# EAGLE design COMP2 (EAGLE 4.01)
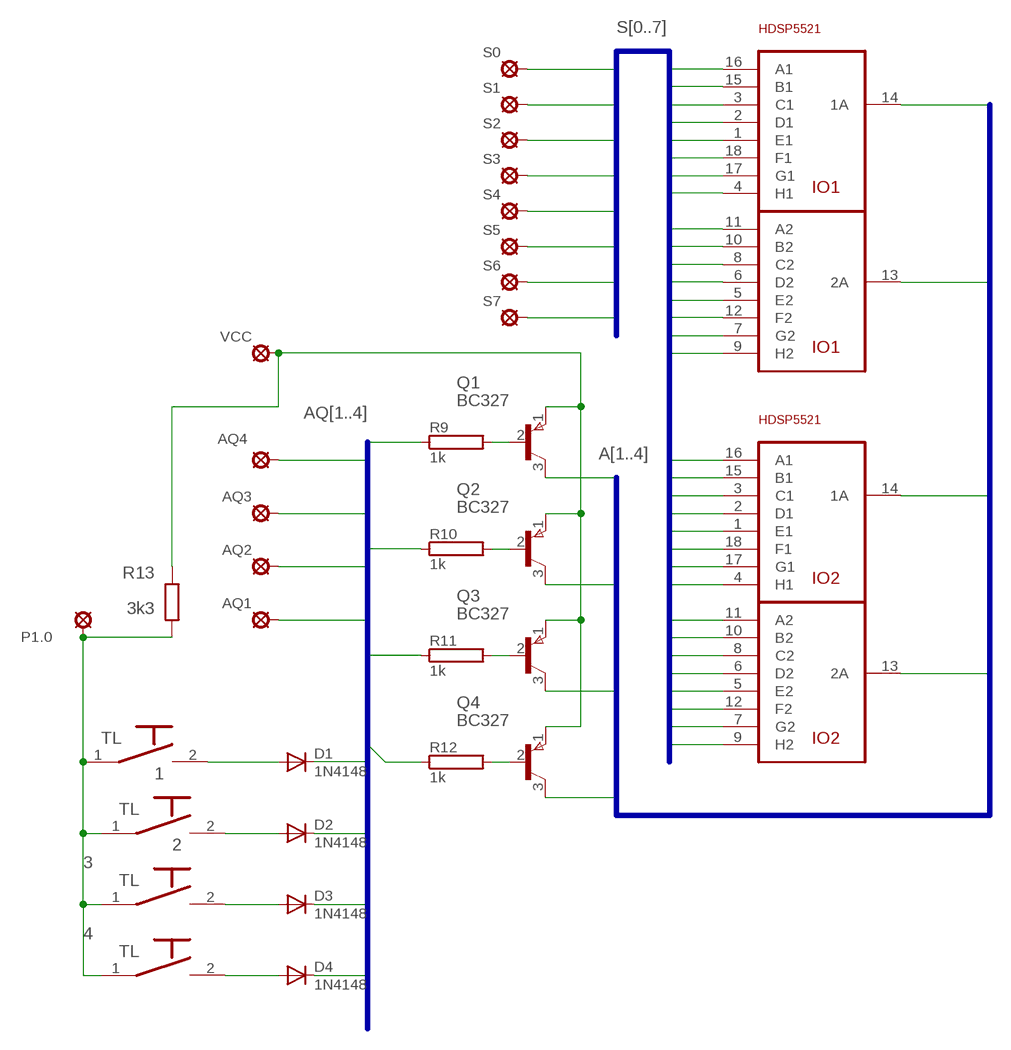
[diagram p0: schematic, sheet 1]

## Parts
1  TL  [TL]
2  TL  [TL]
3  TL  [TL]
4  TL  [TL]
AQ1  LSP10  [LSP10]
AQ2  LSP10  [LSP10]
AQ3  LSP10  [LSP10]
AQ4  LSP10  [LSP10]
D1  1N4148  [DO35-10]
D2  1N4148  [DO35-10]
D3  1N4148  [DO35-10]
D4  1N4148  [DO35-10]
IO1  HDSP5521  [HDSP5521]
IO2  HDSP5521  [HDSP5521]
P1.0  LSP10  [LSP10]
Q1  BC327  [TO92]
Q2  BC327  [TO92]
Q3  BC327  [TO92]
Q4  BC327  [TO92]
R9  1k  0309/10  [0309/10]
R10  1k  0309/10  [0309/10]
R11  1k  0309/10  [0309/10]
R12  1k  0309/10  [0309/10]
R13  3k3  RR-10  [RR-10]
S0  LSP10  [LSP10]
S1  LSP10  [LSP10]
S2  LSP10  [LSP10]
S3  LSP10  [LSP10]
S4  LSP10  [LSP10]
S5  LSP10  [LSP10]
S6  LSP10  [LSP10]
S7  LSP10  [LSP10]
VCC  LSP10  [LSP10]

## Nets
+5V: Q1.1(E) Q2.1(E) Q3.1(E) Q4.1(E) R13.2 VCC.MP
A1: IO1.14(1A) Q1.3(C)
A2: IO1.13(2A) Q2.3(C)
A3: IO2.14(1A) Q3.3(C)
A4: IO2.13(2A) Q4.3(C)
AQ1: AQ1.MP D1.K R9.1
AQ2: AQ2.MP D2.K R10.1
AQ3: AQ3.MP D3.K R11.1
AQ4: AQ4.MP D4.K R12.1
P1.0: 1.1 2.1 3.1 4.1 P1.0.MP R13.1
R9Q1: Q1.2(B) R9.2
R10Q2: Q2.2(B) R10.2
R11Q3: Q3.2(B) R11.2
R12Q4: Q4.2(B) R12.2
S0: IO1.11(A2) IO1.16(A1) IO2.11(A2) IO2.16(A1) S0.MP
S1: IO1.10(B2) IO1.15(B1) IO2.10(B2) IO2.15(B1) S1.MP
S2: IO1.3(C1) IO1.8(C2) IO2.3(C1) IO2.8(C2) S2.MP
S3: IO1.2(D1) IO1.6(D2) IO2.2(D1) IO2.6(D2) S3.MP
S4: IO1.1(E1) IO1.5(E2) IO2.1(E1) IO2.5(E2) S4.MP
S5: IO1.12(F2) IO1.18(F1) IO2.12(F2) IO2.18(F1) S5.MP
S6: IO1.7(G2) IO1.17(G1) IO2.7(G2) IO2.17(G1) S6.MP
S7: IO1.4(H1) IO1.9(H2) IO2.4(H1) IO2.9(H2) S7.MP
TL1.2: 1.2 D1.A
TL2.2: 2.2 D2.A
TL3.1: 4.2 D4.A
TL3.2: 3.2 D3.A

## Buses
S[0..7]
A[1..4]
AQ[1..4]

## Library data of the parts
1-4 = vl1:TL
AQ1-AQ4 P1.0 S0 S1-S7 VCC = SOLPAD:LSP10
D1-D4 = DIODE:1N4148
IO1 IO2 = vl1:HDSP5521
Q1-Q4 = PNP:BC327
R9-R12 = R:0309/10
R13 = GM99:RR-10

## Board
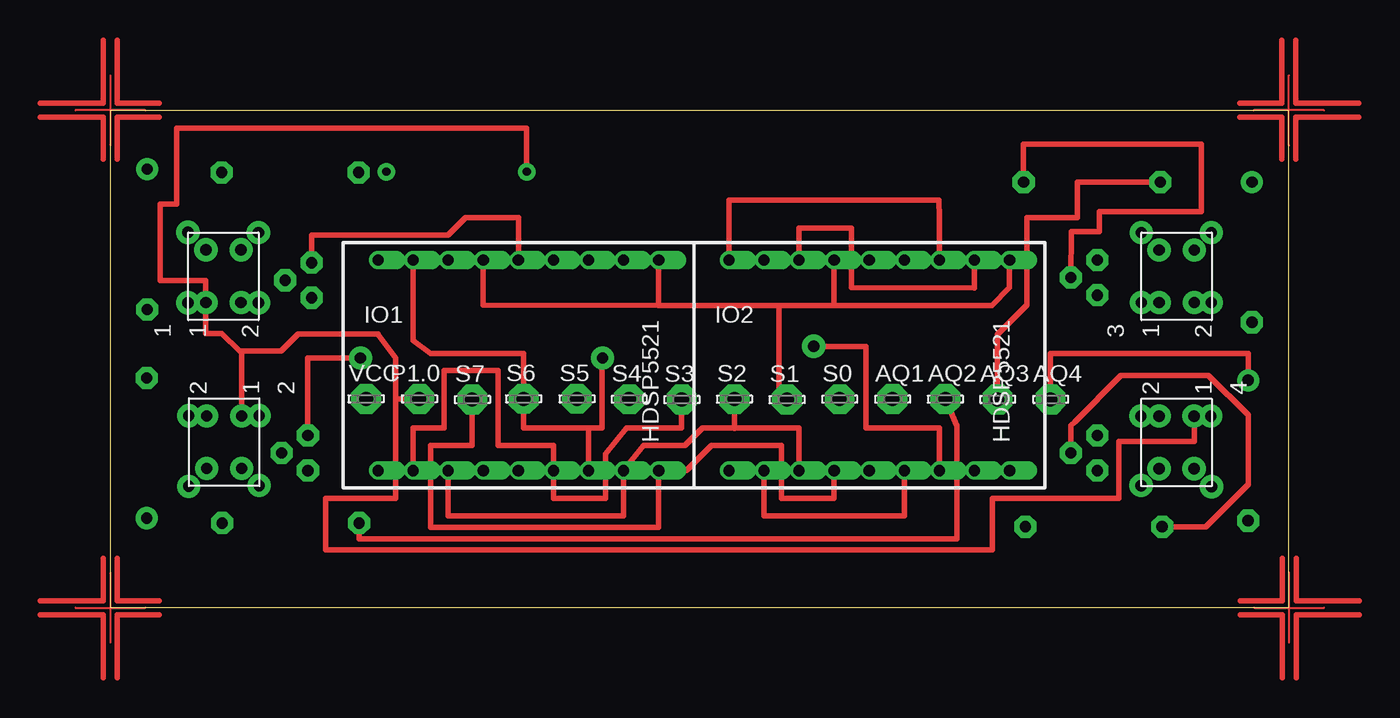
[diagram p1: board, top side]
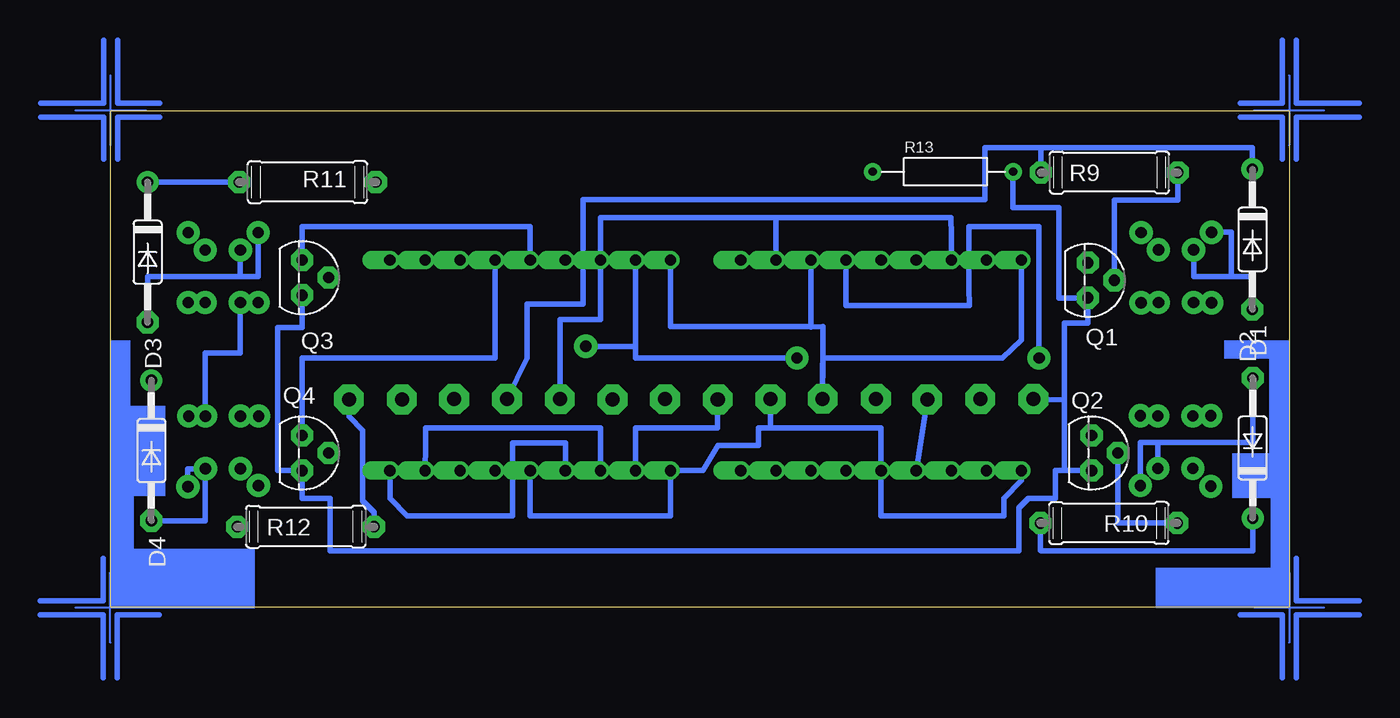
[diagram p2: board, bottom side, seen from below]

Size 85.32 x 36 mm. Coordinates in mm from the lower left corner, seen from the top.
Outline: 0,0 85.32,0 85.32,36 0,36 0,0
Copper layers used: Top, Bottom

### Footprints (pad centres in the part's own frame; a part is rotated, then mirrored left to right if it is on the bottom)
TL = drill 0.813 pad 1.676 round: 1 -6.35,1.27; 2 -2.54,1.27; 3 -6.35,-1.27; 4 -2.54,-1.27
LSP10 = drill 1.016 pad 2.159 octagon: MP 0,0
DO35-10 = drill 0.813 pad 1.6 octagon: A 5.08,0 | drill 0.813 pad 1.6 round: K -5.08,0
HDSP5521 = drill 0.813 pad 1.092 offset: 1 -10.16,-7.62; 2 -7.62,-7.62; 3 -5.08,-7.62; 4 -2.54,-7.62; 5 0,-7.62; 6 2.54,-7.62; 7 5.08,-7.62; 8 7.62,-7.62; 9 10.16,-7.62; 10 10.16,7.62; 11 7.62,7.62; 12 5.08,7.62; 13 2.54,7.62; 14 0,7.62; 15 -2.54,7.62; 16 -5.08,7.62; 17 -7.62,7.62; 18 -10.16,7.62
TO92 = drill 0.813 pad 1.6 octagon: 1 1.27,0; 2 0,1.905; 3 -1.27,0
0309/10 = drill 0.813 pad 1.6 octagon: 1 -4.953,0; 2 4.953,0
RR-10 = drill 0.61 pad 1.27 round: 1 0,0; 2 10.16,0

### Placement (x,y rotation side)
1  8.19,28.44 90 top
2  8.24,7.53 270 top
3  77.2,28.44 90 top
4  77.19,7.51 270 top
AQ1  56.63,15.1 0 top
AQ2  60.45,15.1 0 top
AQ3  64.23,15.08 0 top
AQ4  68.07,15.08 0 top
D1  2.67,26.67 270 bottom
D2  2.64,11.55 90 bottom
D3  82.65,25.74 270 bottom
D4  82.37,11.37 270 bottom
IO1  29.54,17.54 0 top
IO2  54.94,17.54 0 top
P1.0  22.37,15.11 0 top
Q1  14.57,23.7 270 bottom
Q2  14.3,11.19 270 bottom
Q3  71.45,23.89 270 bottom
Q4  71.45,11.19 270 bottom
R9  13.01,31.51 0 bottom
R10  13.05,6.12 0 bottom
R11  71.07,30.81 0 bottom
R12  71.2,5.86 180 bottom
R13  30.15,31.57 0 bottom
S0  52.8,15.09 0 top
S1  48.99,15.07 0 top
S2  45.18,15.09 0 top
S3  41.37,15.07 0 top
S4  37.56,15.09 0 top
S5  33.77,15.12 0 top
S6  29.91,15.12 0 top
S7  26.2,15.07 0 top
U$1  [ROH]  0,36.01 270 top
U$2  [ROH]  0,0 0 top
U$3  [ROH]  85.34,0 90 top
U$4  [ROH]  85.32,36.01 180 top
VCC  18.52,15.11 0 top

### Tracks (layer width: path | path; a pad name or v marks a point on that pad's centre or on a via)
+5V
  Bottom 0.406: Q3.1 71.45,20.26 73.23,20.26 73.23,9.92 Q4.1 71.45,7.92 69.42,7.92 69.42,4.11 19.56,4.11 19.56,7.23 18.9,7.89 16.92,7.89 16.92,9.92 | 14.83,20.62 16.28,20.62 16.28,15.03 | 16.28,15.03 VCC.MP | R13.2 19.99,28.95 16.69,28.95 16.69,22.42 Q1.1 | Q1.1 14.55,22.42 | Q1.1 14.57,20.62 14.83,20.62 | 14.83,20.62 14.64,20.62 | Q2.1 16.92,9.92 | 16.92,9.92 16.28,9.92 16.28,15.03
A1
  Top 0.406: Q1.3 14.59,26.33 14.59,26.97 24.46,26.97 25.73,28.24 29.54,28.24 IO1.14
A2  (via drill 0.81 pad 1.68)
  Top 0.406: Q2.3 14.3,17.62 14.3,18.08 v18.11,18.08
  Bottom 0.406: v18.11,18.08 18.11,27.6 23.19,27.6 23.19,23.16 23.16,21.89 32.08,21.89 IO1.13
A3
  Bottom 0.406: Q3.3 71.45,27.58 54.94,27.58 IO2.14
A4
  Bottom 0.406: Q4.3 71.45,18.08 57.48,18.08 IO2.13
AQ1
  Bottom 0.406: 2.67,33.32 18,33.32 | R9.1 17.98,33.29 17.98,33.32 18,33.32 | AQ1.MP 55.17,18.08 55.17,18.26 55.18,21.99 51.13,21.99 51.13,28.24 51.1,29.56 22.02,29.56 22.02,33.32 18,33.32 | 2.67,33.32 2.67,33.3 | D1.K 2.67,33.32
AQ2
  Top 0.406: AQ2.MP 61.29,13.15 61.29,4.99 18.01,4.99 18.01,5.34 R10.1
  Bottom 0.406: R10.1 18.01,4.14 17.96,4.11 2.67,4.11 2.64,4.11 | 2.64,4.11 2.64,4.12 | 2.64,4.11 D2.K
AQ3
  Top 0.406: R11.1 70.01,30.82 70.01,28.24 66.37,28.24 66.37,21.92 64.23,19.78 AQ3.MP
  Bottom 0.406: R11.1 D3.K
AQ4
  Top 0.406: 82.09,18.4 68.07,18.4 AQ4.MP | 82.09,18.4 82.36,18.4 | D4.K 82.37,18.4 82.09,18.4
  Bottom 0.406: R12.1 66.24,6.89 67.08,7.73 67.08,8.31 67.08,8.28 67.07,12.81 67.06,12.81 68.07,13.82 AQ4.MP
N$1  (via drill 0.81 pad 1.68)
  other vias: 79.73,8.76
N$2  (via drill 0.81 pad 1.68)
  other vias: 74.62,8.83
P1.0
  Top 0.406: 73,7.92 63.84,7.92 63.86,4.19 15.58,4.17 15.58,7.92 20.65,7.92 20.65,15.11 | 73,7.92 73.01,8.73 | 20.65,15.11 P1.0.MP | 20.65,15.11 20.65,15.08 | 20.65,15.11 20.65,18.08 19.38,19.78 19.38,19.81 13.61,19.81 12.37,18.56 9.5,18.56 | 9.5,18.56 9.35,18.56 8.08,19.83 6.91,19.83 1.1 6.91,23.67 3.61,23.67 3.61,29.23 4.8,29.23 4.8,34.72 30.15,34.72 R13.1 | 2.1 9.51,18.56 9.5,18.56 | 4.1 78.46,12.03 73,12.03 73,7.92
  Bottom 0.406: 4.1 78.46,18.44 76.1,18.44 | 76.1,18.44 76.07,18.44 | 3.1 75.93,18.44 76.1,18.44
R9Q1
  Bottom 0.406: 12.27,29.51 8.36,29.51 | 12.27,29.51 12.47,29.51 | Q1.2 12.66,29.51 12.27,29.51 | 8.36,29.51 8.2,29.51 | R9.2 8.06,29.51 8.36,29.51
R10Q2
  Bottom 0.406: R10.2 12.39,6.12 Q2.2
R11Q3
  Top 0.406: Q3.2 69.57,27.22 71.59,27.22 71.59,28.68 78.99,28.68 78.99,33.55 78.83,33.55 66.12,33.55 R11.2
R12Q4
  Top 0.406: Q4.2 69.54,13.18 69.81,13.43 73.15,16.82 79.49,16.82 82.37,13.94 82.37,8.91 79.32,5.86 R12.2
S0
  Top 0.406: IO2.11 62.56,23.13 53.67,23.16 53.67,27.49 49.86,27.49 IO2.16
  Bottom 0.406: 37.16,28.24 24.49,28.24 24.46,26.97 IO1.16 | 37.16,28.24 IO1.11 | S0.MP 52.79,20.86 49.86,20.86 IO2.16 49.86,28.24 37.16,28.24
S1
  Top 0.406: 39.7,21.89 27,21.9 IO1.15 | 39.7,21.89 IO1.10 | 48.41,21.86 48.41,15.54 S1.MP | 48.41,21.86 52.4,21.86 52.4,21.89 | 52.4,21.89 IO2.15 | 52.4,21.89 63.83,21.89 65.1,23.16 IO2.10 | 39.7,21.89 48.59,21.89 48.41,21.86
S2
  Top 0.406: IO1.3 24.46,6.65 37.16,6.65 IO1.8 38.61,11.73 41.2,11.73 41.6,11.73 42.87,13 44.7,13 | 44.7,13 45.17,12.99 S2.MP | 44.7,13 49.86,13 IO2.3
  Bottom 0.406: IO2.8 62.53,11.78 62.53,13 49.86,13 IO2.3
S3
  Top 0.406: IO1.2 21.92,13.01 24.16,13.01 24.16,17.17 28.07,17.17 28.07,11.73 32.09,11.73 32.08,10.46 IO1.6 32.08,7.92 35.86,7.92 35.86,8.02 | IO2.6 57.48,6.65 47.32,6.65 IO2.2 | S3.MP 41.37,13 37.36,13 35.86,11.12 35.86,8.02 | 35.86,8.02 35.86,7.93
  Bottom 0.406: IO2.2 47.32,13 41.38,13 S3.MP
S4
  Bottom 0.406: IO1.1 19.38,9.19 20.65,7.92 20.65,6.65 29.54,6.65 IO1.5 29.54,13 37.5,13 | 44.78,6.65 54.94,6.65 IO2.5 | 37.56,13 S4.MP | 37.56,13 37.57,13 | 44.78,6.65 44.78,6.62 | 44.78,6.65 IO2.1 42.44,9.93 41.35,11.73 38.43,11.73 38.43,13 37.5,13 | 37.5,13 37.56,13
S5
  Top 0.406: IO2.12 60.02,28.24 59.98,29.51 44.78,29.51 IO2.18
  Bottom 0.406: 34.62,20.34 34.62,20.33 33.76,20.35 S5.MP 33.77,18.07 32.08,18.08 20.78,18.08 19.38,19.38 IO1.18 | 34.62,20.34 44.78,20.34 IO2.18 | 34.62,20.34 IO1.12
S6  (via drill 0.81 pad 1.68)
  Top 0.406: 35.59,13 29.92,13 S6.MP 29.92,18.38 23.19,18.38 21.92,19.35 IO1.17 | 51.03,18.92 54.71,18.92 54.69,13 60.02,13 IO2.7 | 35.59,13 35.59,18.08 | v50.93,18.92 51.03,18.92 | 51.03,18.92 51.03,18.82 | 35.59,18.08 v35.64,18.08 35.64,17.88 | 35.59,18.08 35.59,18.13 | IO1.7 34.62,13 35.59,13
  Bottom 0.406: 35.59,18 35.59,18.08 v35.64,18.08 47.32,18.08 47.32,19.38 | v50.93,18.92 47.32,18.92 47.32,19.38 | 47.32,19.38 IO2.17
S7
  Top 0.406: IO2.4 52.4,7.92 48.59,7.92 48.59,11.73 43.51,11.73 41.7,9.92 IO1.9 39.7,5.81 23.18,5.8 23.19,6.65 23.19,11.73 26.2,11.73 S7.MP
  Bottom 0.406: IO2.9 65.1,7.92 63.86,6.65 56.21,6.65 56.21,11.91 52.4,11.91 IO2.4 | IO1.4 26.75,11.58 S7.MP
S$2  (via drill 0.81 pad 1.68)
  other vias: 5.61,22.07
S$3  (via drill 0.81 pad 1.68)
  other vias: 10.72,22.07
S$4  (via drill 0.81 pad 1.68)
  other vias: 10.72,27.15
S$5  (via drill 0.81 pad 1.68)
  other vias: 5.66,13.89
S$6  (via drill 0.81 pad 1.68)
  other vias: 10.77,13.89
S$7  (via drill 0.81 pad 1.68)
  Bottom 0.406: 9.47,11.91 9.45,11.96 10.77,11.96 v10.77,8.83
S$8  (via drill 0.81 pad 1.68)
  other vias: 5.66,8.78
S$9  (via drill 0.81 pad 1.68)
  other vias: 74.6,13.86
S$10  (via drill 0.81 pad 1.68)
  other vias: 79.68,13.86
S$12  (via drill 0.81 pad 1.68)
  other vias: 74.65,22.09
S$13  (via drill 0.81 pad 1.68)
  other vias: 79.7,22.09
S$14  (via drill 0.81 pad 1.68)
  other vias: 79.7,27.15
S$16  (via drill 0.81 pad 1.68)
  Bottom 0.406: v74.65,27.15 74.65,23.97 75.87,23.97
S$17  (via drill 0.81 pad 1.68)
  Bottom 0.406: v5.61,27.17 4.19,27.17 4.19,23.97
TL1.2
  Bottom 0.406: 1.2 6.92,23.99 6.91,23.97 2.79,23.97 2.76,23.97 2.67,23.97 D1.A
TL2.2
  Bottom 0.406: 2.2 9.51,11.96 2.84,11.96 | 2.84,11.96 2.64,11.96 | D2.A 2.64,11.96 2.84,11.96
TL3.1
  Bottom 0.406: 78.46,7.06 78.46,6.46 78.46,6.29 D4.A | 78.46,7.06 78.46,7.16 | 78.46,7.06 4.2 79.73,10.05 79.73,8.83
TL3.2
  Bottom 0.406: 82.5,23.97 75.92,23.97 75.93,24 3.2 | 82.5,23.97 82.58,23.97 | D3.A 82.65,23.97 82.5,23.97
(copper drawn outside any net)
  shapes: Bottom area x12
